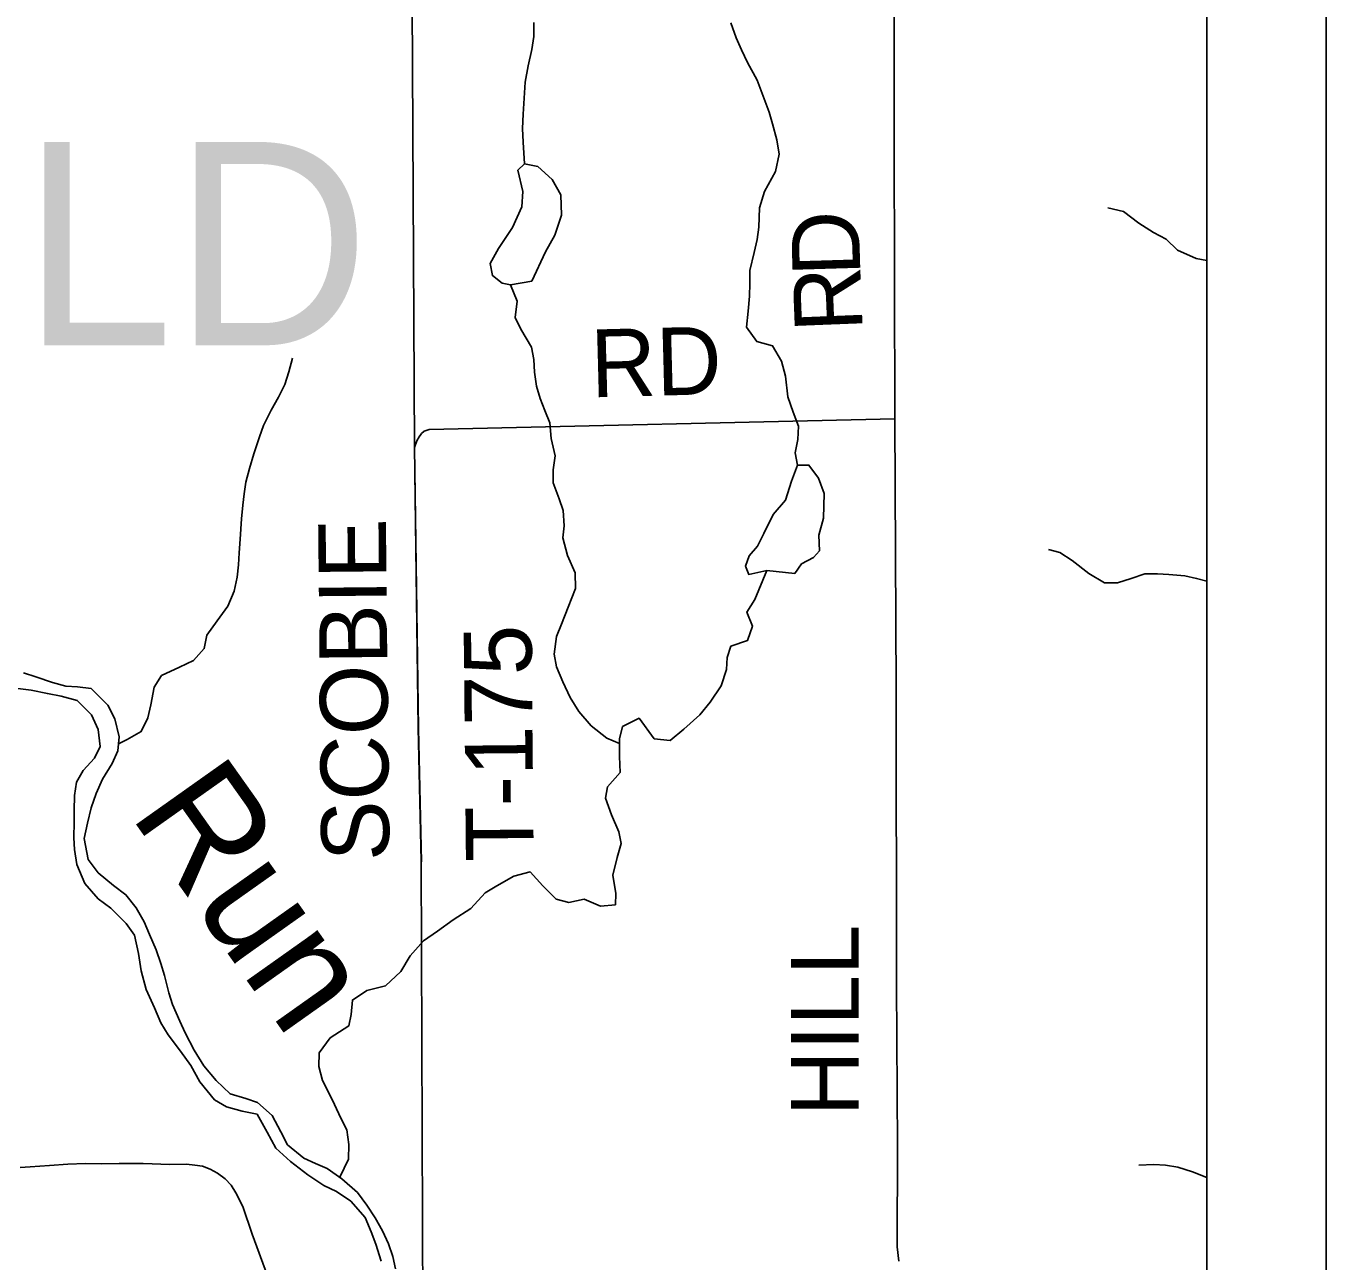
# Model space of a CAD drawing. Extents: x 0 to 34, y 0 to 22.
# Drawn here: x 7.911 to 9, y 16.905 to 17.94 of the extents above; entities that cross this region are included whole.
import ezdxf

# ---------------------------------------------------------------- set-up
doc = ezdxf.new("R2010")
doc.units = 0
for name, color, linetype in [('Default', 7, 'Continuous'), ('GM_X_County_Road', 7, 'Continuous'), ('GM_X_Minor_Lake', 7, 'Continuous'), ('GM_X_Minor_River', 7, 'Continuous'), ('GM_X_Minor_River_Text', 7, 'Continuous'), ('GM_X_Township_Road', 7, 'Continuous'), ('GM_X_Township_Road_Text', 7, 'Continuous'), ('GM_X_Township_Text', 7, 'Continuous'), ('SH_Cut_Line', 7, 'Continuous'), ('SH_Data', 7, 'Continuous')]:
    doc.layers.add(name, color=color, linetype=linetype)

msp = doc.modelspace()

# ---------------------------------------------------------------- linework, layer by layer
at = {"layer": 'Default'}
msp.add_lwpolyline([(8.9, 15.9304), (8.9, 20.9), (8.1749, 20.9), (8.1859, 20.3892), (8.1995, 19.7718), (8.2061, 19.4737), (8.2069, 19.4369), (8.2195, 18.875), (8.2216, 18.8361), (8.2229, 18.8136), (8.2232, 18.7798), (8.2237, 18.7271), (8.2254, 18.6464), (8.2283, 18.4271), (8.2338, 18.0126), (8.2361, 17.5877), (8.2392, 17.3521), (8.2417, 17.2403), (8.2434, 16.7876), (8.2536, 16.1438), (8.2582, 15.9227), (8.4608, 15.9241), (8.569, 15.9256)], close=True, dxfattribs=at)
msp.add_lwpolyline([(6.5781, 15.8955), (6.9232, 15.9027), (7.0184, 15.9049), (7.3026, 15.9113), (7.5392, 15.9156), (8.2582, 15.9227), (8.2536, 16.1438), (8.2434, 16.7876), (8.2417, 17.2403), (8.2392, 17.3521), (8.2361, 17.5877), (8.2338, 18.0126), (8.2283, 18.4271), (8.2254, 18.6464), (8.2237, 18.7271), (8.2232, 18.7798), (8.2229, 18.8136), (8.2216, 18.8361), (8.2195, 18.875), (8.2069, 19.4369), (8.2061, 19.4737), (8.1995, 19.7718), (8.1859, 20.3892)], dxfattribs=at)
at = {"layer": 'GM_X_County_Road'}
msp.add_lwpolyline([(7.9058, 16.9834), (7.914, 16.9841), (7.9302, 16.9852), (7.9456, 16.9863), (7.9606, 16.9868), (7.9736, 16.9866), (7.9886, 16.9868), (8.0087, 16.9868), (8.0311, 16.9861), (8.045, 16.9864), (8.0522, 16.9856), (8.0586, 16.9846), (8.0649, 16.982), (8.0711, 16.9788), (8.0774, 16.9739), (8.0824, 16.9687), (8.0865, 16.9623), (8.0924, 16.9507), (8.1, 16.9277), (8.113, 16.8928)], dxfattribs=at)
at = {"layer": 'GM_X_Minor_Lake'}
for points in [[(8.3345, 17.7265), (8.346, 17.7509), (8.3539, 17.765), (8.3594, 17.7818), (8.3589, 17.7989), (8.3516, 17.8117), (8.3394, 17.8226), (8.3284, 17.8248), (8.3227, 17.8194), (8.327, 17.8016), (8.326, 17.7887), (8.3182, 17.7715), (8.3066, 17.7539), (8.2995, 17.7413), (8.3015, 17.7311), (8.3095, 17.7247), (8.3167, 17.7233)], [(8.3167, 17.7233), (8.3345, 17.7265)], [(8.5549, 17.4813), (8.5606, 17.4894), (8.5704, 17.4948), (8.5756, 17.5005), (8.5751, 17.5134), (8.5788, 17.5279), (8.5794, 17.5484), (8.5747, 17.5613), (8.5667, 17.5722), (8.5572, 17.5721), (8.552, 17.5588), (8.5472, 17.5428), (8.5367, 17.5309), (8.5289, 17.5149), (8.5237, 17.5042), (8.5165, 17.4962), (8.5136, 17.4874), (8.5163, 17.4806), (8.5238, 17.4822), (8.5314, 17.4838)], [(8.5314, 17.4838), (8.5549, 17.4813)]]:
    msp.add_lwpolyline(points, dxfattribs=at)
at = {"layer": 'GM_X_Minor_River'}
for points in [[(8.3284, 17.8248), (8.3271, 17.843), (8.3266, 17.8544), (8.3272, 17.8665), (8.3289, 17.8931), (8.3314, 17.9068), (8.3344, 17.9205), (8.3362, 17.9316), (8.3361, 17.9433)], [(8.5572, 17.5721), (8.5552, 17.5824), (8.5574, 17.5938), (8.558, 17.6048), (8.5534, 17.6165), (8.5491, 17.6294), (8.5471, 17.6468), (8.5436, 17.6593), (8.5362, 17.6722), (8.5229, 17.6759), (8.5145, 17.6879), (8.5159, 17.7012), (8.5169, 17.7138), (8.5172, 17.7244), (8.5171, 17.7354), (8.5208, 17.7503), (8.5234, 17.7613), (8.5248, 17.7716), (8.5254, 17.7879), (8.5295, 17.8016), (8.5388, 17.8184), (8.5417, 17.8329), (8.5397, 17.845), (8.5362, 17.8583), (8.5334, 17.8681), (8.5292, 17.8791), (8.5233, 17.895), (8.5153, 17.9097), (8.5102, 17.9203), (8.5056, 17.9305), (8.5013, 17.943)], [(8.9, 17.7436), (8.8912, 17.7454), (8.8756, 17.7525), (8.866, 17.7615), (8.8554, 17.7671), (8.8432, 17.775), (8.8302, 17.7847), (8.8173, 17.788)], [(8.4079, 17.339), (8.3973, 17.3435), (8.3843, 17.3536), (8.374, 17.3657), (8.3667, 17.3774), (8.3605, 17.3906), (8.3551, 17.4031), (8.3531, 17.4137), (8.3552, 17.4285), (8.3593, 17.4388), (8.3649, 17.4533), (8.3712, 17.4689), (8.3707, 17.4819), (8.3645, 17.4966), (8.3606, 17.5114), (8.3617, 17.5213), (8.3608, 17.5342), (8.3573, 17.544), (8.3523, 17.5573), (8.3525, 17.5683), (8.354, 17.5801), (8.3508, 17.5945), (8.3495, 17.6077), (8.3453, 17.618), (8.3414, 17.6282), (8.3383, 17.6384), (8.3367, 17.6502), (8.3362, 17.6608), (8.3342, 17.671), (8.3254, 17.6861), (8.3204, 17.696), (8.3221, 17.7096), (8.3167, 17.7233)], [(7.9881, 17.3386), (7.9955, 17.3423), (8.0072, 17.3489), (8.0128, 17.3603), (8.0153, 17.3714), (8.0179, 17.3862), (8.0242, 17.3958), (8.0393, 17.4028), (8.051, 17.4086), (8.06, 17.4185), (8.0622, 17.4296), (8.0708, 17.4418), (8.0798, 17.454), (8.085, 17.4666), (8.0876, 17.4784), (8.0886, 17.4887), (8.0893, 17.4986), (8.09, 17.5103), (8.0913, 17.5271), (8.0924, 17.5388), (8.0934, 17.5483), (8.0949, 17.5579), (8.0978, 17.5693), (8.1015, 17.5818), (8.1063, 17.5959), (8.1096, 17.6055), (8.116, 17.6184), (8.1223, 17.6291), (8.1275, 17.6398), (8.1308, 17.6505), (8.1338, 17.6619)], [(8.8589, 17.4812), (8.8483, 17.4811), (8.8366, 17.4772), (8.8253, 17.4736), (8.8143, 17.4735), (8.8013, 17.4814), (8.7872, 17.4923), (8.7769, 17.499), (8.7674, 17.5016)], [(8.1737, 16.9753), (8.1808, 16.9905), (8.1811, 17.0027), (8.1795, 17.0152), (8.1745, 17.025), (8.1691, 17.0364), (8.1641, 17.0466), (8.159, 17.0564), (8.1559, 17.0681), (8.1562, 17.0795), (8.1656, 17.0922), (8.181, 17.1022), (8.1832, 17.1117), (8.1842, 17.1239), (8.1963, 17.1319), (8.2118, 17.1359), (8.2246, 17.1478), (8.2324, 17.1608), (8.2437, 17.1734), (8.2554, 17.1815), (8.2686, 17.1911), (8.2833, 17.2007), (8.2953, 17.2138), (8.3051, 17.2196), (8.3194, 17.2277), (8.3331, 17.2312), (8.3438, 17.2196), (8.3549, 17.2083), (8.3655, 17.2057), (8.3784, 17.2085), (8.3921, 17.2025), (8.4046, 17.2038), (8.4048, 17.2133), (8.4024, 17.2285), (8.4061, 17.2433), (8.4094, 17.2551), (8.4074, 17.265), (8.4013, 17.279), (8.3962, 17.293), (8.398, 17.3025), (8.4085, 17.3147), (8.408, 17.328), (8.4079, 17.3428), (8.4105, 17.3531), (8.4244, 17.3601), (8.4371, 17.3427), (8.4504, 17.3413), (8.462, 17.3509), (8.4752, 17.3628), (8.4838, 17.3736), (8.4932, 17.3873), (8.4976, 17.401), (8.4983, 17.4109), (8.5013, 17.4204), (8.5152, 17.4251), (8.5193, 17.4373), (8.5147, 17.449), (8.5214, 17.4597), (8.5314, 17.4838)], [(8.9, 17.4749), (8.8916, 17.4773), (8.8817, 17.4795), (8.8684, 17.4805), (8.8589, 17.4812)], [(8.2203, 16.8986), (8.2179, 16.9088), (8.2144, 16.9194), (8.2094, 16.9304), (8.2032, 16.9414), (8.1963, 16.9519), (8.1883, 16.9625), (8.1753, 16.9741), (8.1631, 16.9828), (8.1532, 16.9868), (8.1433, 16.9913), (8.1296, 17.0026), (8.1242, 17.0135), (8.1168, 17.0271), (8.1046, 17.038), (8.0947, 17.0413), (8.0818, 17.0454), (8.07, 17.0563), (8.0596, 17.0687), (8.0516, 17.082), (8.0439, 17.0963), (8.0396, 17.1061), (8.0334, 17.1201), (8.0303, 17.13), (8.0268, 17.1444), (8.0236, 17.1546), (8.0198, 17.166), (8.014, 17.1788), (8.0097, 17.1894), (8.0028, 17.2011), (7.9943, 17.2121), (7.984, 17.2199), (7.9711, 17.2304), (7.9626, 17.2418), (7.9594, 17.2592), (7.962, 17.2721), (7.9653, 17.2851), (7.9694, 17.2969), (7.9746, 17.3091), (7.9828, 17.3221), (7.9876, 17.3328), (7.9887, 17.3445), (7.9851, 17.3597), (7.9793, 17.371), (7.9652, 17.385), (7.9538, 17.3864), (7.9439, 17.387), (7.9329, 17.39), (7.9189, 17.3948), (7.9086, 17.3981)], [(7.9038, 17.3851), (7.9148, 17.3837), (7.9285, 17.3808), (7.9402, 17.3787), (7.9535, 17.375), (7.9654, 17.3629), (7.9712, 17.3505), (7.9728, 17.3364), (7.968, 17.3265), (7.9586, 17.3162), (7.953, 17.3066), (7.9512, 17.2952), (7.9509, 17.2827), (7.951, 17.2732), (7.9507, 17.2599), (7.9512, 17.25), (7.9532, 17.2375), (7.9598, 17.2216), (7.9712, 17.2088), (7.9816, 17.2009), (7.9945, 17.1881), (8.0015, 17.1783), (8.005, 17.1628), (8.007, 17.1484), (8.0113, 17.1328), (8.0183, 17.1173), (8.0237, 17.1049), (8.0298, 17.0947), (8.0402, 17.0811), (8.0486, 17.069), (8.0563, 17.0554), (8.0686, 17.0403), (8.0785, 17.0344), (8.0918, 17.0307), (8.1043, 17.0281), (8.1128, 17.013), (8.1201, 16.9998), (8.1323, 16.9885), (8.1468, 16.9773), (8.1602, 16.9683), (8.1708, 16.9635), (8.1827, 16.9552), (8.1949, 16.9417), (8.1999, 16.9296), (8.2038, 16.9193), (8.2081, 16.9049)], [(8.9, 16.9752), (8.8882, 16.9798), (8.8757, 16.9838), (8.8655, 16.9856), (8.8556, 16.9859), (8.8431, 16.9854)]]:
    msp.add_lwpolyline(points, dxfattribs=at)
at = {"layer": 'GM_X_Township_Road'}
for points in [[(8.6421, 16.9049), (8.6406, 16.917), (8.6409, 17.0012), (8.6401, 17.1369), (8.6397, 17.3846), (8.6386, 17.6111), (8.6381, 17.8456), (8.6382, 18.015)], [(8.2414, 17.5978), (8.2421, 17.5987), (8.2443, 17.6006), (8.2485, 17.602), (8.6386, 17.6111)], [(8.2419, 17.2398), (8.2394, 17.3515), (8.2363, 17.5871), (8.2382, 17.5926), (8.2401, 17.596), (8.2414, 17.5978)]]:
    msp.add_lwpolyline(points, dxfattribs=at)
at = {"layer": 'SH_Cut_Line'}
msp.add_lwpolyline([(3.2807, 14.1), (8.9, 14.1), (8.9, 20.9), (3.2826, 20.9), (3.2843, 20.6124), (3.2845, 20.5998), (3.2888, 19.8918), (3.2901, 19.68), (3.2904, 19.1173), (3.2907, 18.4315), (3.2837, 17.3796), (3.2835, 17.0107), (3.2832, 16.3898), (3.2829, 15.8433), (3.2815, 15.7537), (3.2811, 15.7294), (3.2832, 14.8896), (3.2841, 14.501), (3.2822, 14.2781), (3.2808, 14.1155)], close=True, dxfattribs=at)
at = {"layer": 'SH_Data'}
for p, q in [((9, 21), (9, 14)), ((8.9, 20.9), (8.9, 14.1))]:
    msp.add_line(p, q, dxfattribs=at)

# ---------------------------------------------------------------- texts
at = {"layer": 'GM_X_Minor_River_Text'}
msp.add_text('Run', height=0.09475, rotation=305.3302, dxfattribs=at).set_placement((7.9968, 17.2795))
at = {"layer": 'GM_X_Township_Road_Text'}
for s, height, rotation, p in [('D', 0.0568, 91.7196, (8.6099, 17.7314)), ('R', 0.0568, 92.2839, (8.6118, 17.6849)), ('RD', 0.05682, 1.4806, (8.3844, 17.629)), ('SCOBIE', 0.05682, 90.5804, (8.2151, 17.2406)), ('T-175', 0.05682, 90.5614, (8.3361, 17.2401)), ('HILL', 0.05682, 90, (8.6084, 17.0266))]:
    msp.add_text(s, height=height, rotation=rotation, dxfattribs=at).set_placement(p)
at = {"layer": 'GM_X_Township_Text'}
msp.add_text('RICHFIELD', height=0.17045, rotation=0, dxfattribs=at).set_placement((6.9956, 17.6727))

doc.saveas('drawing.dxf')
